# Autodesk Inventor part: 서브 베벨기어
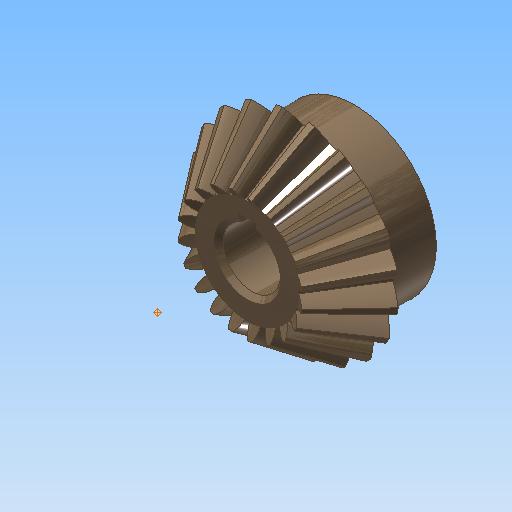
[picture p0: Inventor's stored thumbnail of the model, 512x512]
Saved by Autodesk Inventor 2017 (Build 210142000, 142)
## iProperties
Created: 2014-10
Part Number: 서브 베벨기어
Material: 강철, 탄소
Document SubType Name: Modeling
Designer: KYOUNG IL JANG
Categories: <?xml version="1.0" encoding="UTF-16"?> <MemberInstance><Categories><FamilyTemplate><FamilyTemplateParameter ValueType="xs:double" Id="1" ObjectReferenceKey="da
Mass: 135.037 g
Surface Area: 63.6518 cm^2
Volume: 17.1585 cm^3
Density: 7.87 g/cm^3
Appearance: 얼룩무늬
CustomPartVersion: 1
Revision Number: 1
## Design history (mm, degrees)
node "맨 위 점"
node "메쉬 평면2"
sketch "톱니 본체 스케치"
  geometry: L1 (0, 0)-(18.003, -31.331); L2 (18.003, -31.331)-(21.664, -28.891); L3 (21.664, -28.891)-(0, 0); L4 (20, -30)-(0, 0); L5 (10.813, -18.818)-(13.012, -17.352); L6 (18.003, -31.331)-(10.813, -18.818); L7 (21.664, -28.891)-(13.012, -17.352); L8 (0, -39.387)-(0, 6.564) reference; L9 (0, -30)-(21.664, -30)
  constraints: 16 end point, 4 point on line, 3 perpendicular, 2 collinear, 1 horizontal alignment, 1 vertical alignment
  dimensions: "d0" = 40 diameter of L4.start L8 (= da_de); "d1" = 36.00616 diameter of L1.end L8 (= da_dfe); "d2" = 43.3282 diameter of L2.end L8 (= da_dae); "d3" = 14.4 distance between parallel lines of L2 L5 (= da_b); "d4" = 28.8906 vertical distance of L2.end L1.start (= da_ve)
revolve "톱니 본체" sketch "톱니 본체 스케치" stored, may be unused: angle "d5" = 90 deg
node "시작점"
node "톱니 평면"
sketch "시작 스케치"
  geometry: L1 (0, -23.505)-(0, 10.645) reference; L2 (-0.834, -2.928)-(0.834, -2.928); A1 r 8.898 centre (-9.698, -3.713) between (-0.834, -2.928) and (-3.903, 3.04); A2 r 8.898 centre (9.698, -3.713) between (3.903, 3.04) and (0.834, -2.928); A3 r 27.357 centre (0, -24.037) between (3.903, 3.04) and (-3.903, 3.04); 1 further point
  constraints: 6 point on circle, 3 centre point, 3 symmetric about line, 2 end point, 1 coincident, 1 perpendicular, 1 other
  dimensions: "d7" = 8.89846 radius of A1 (= fd_rr); "d8" = 9.69794 horizontal distance of point (0, -24.037) A1.centre (= fd_x); "d9" = 20.32439 vertical distance of point (0, -24.037) A1.centre (= fd_y); "d57" = 27.35701 radius of A3 (= 0.5 x fd_dva + 0.3 x da_he); "d58" = 21.10901 distance from line of A3.centre L2 (= 0.5 x fd_dva - 1.12 x da_he)
node "끝점"
  node "끝 평면"
sketch "3D 스케치 오른쪽"
  node "Helical Curve Right" dims "d65" = 229.90621 (computed from da_dm, da_delta, da_beta), "d66" = 31.5, "d67" = 40 (= da_de), "d68" = -5.88003 (= -da_delta), "d69" = 12.16458 (computed from fd_loft, da_delta)
node "끝 평면 오른쪽"
sketch "끝 스케치 오른쪽"
  geometry: L1 (0, -22.649)-(0, 12.15) reference; L2 (-0.497, -1.72)-(0.497, -1.72); A1 r 5.299 centre (-5.775, -2.187) between (-0.497, -1.72) and (-2.324, 1.834); A2 r 5.299 centre (5.775, -2.187) between (2.324, 1.834) and (0.497, -1.72); A3 r 16.291 centre (0, -14.29) between (2.324, 1.834) and (-2.324, 1.834); 1 further point
  constraints: 6 point on circle, 3 centre point, 3 symmetric about line, 2 end point, 1 coincident, 1 perpendicular, 1 other
  dimensions: "d70" = 5.77526 horizontal distance of A3.centre A1.centre (computed from fd_x, fd_ratio); "d71" = 12.10346 vertical distance of point (0, -14.29) A1.centre (computed from fd_y, fd_ratio); "d72" = 5.29916 radius of A1 (computed from fd_rr, fd_ratio); "d73" = 12.57071 distance from line of point (0, -14.29) L2 (computed from d58, fd_ratio); "d74" = 16.29149 radius of A3 (computed from d57, fd_ratio)
feature "로프트 오른쪽" sketch "끝 스케치 오른쪽" dims "d75" = 0, "d77" = 0, "d79" = 0, "d80" = 90 deg, "d85" = 20, "d92" = 90 deg, "d93" = 90 deg, "da_teethtype" = 0 [user parameter]
sketch "3D 스케치 왼쪽"
  node "Helical Curve Left" dims "d26" = 229.90621 (computed from da_dm, da_delta, da_beta), "d27" = 12.16458 (computed from fd_loft, da_delta), "d28" = 40 (= da_de), "d29" = -5.88003 (= -da_delta)
node "끝 평면 왼쪽"
sketch "끝 스케치 왼쪽" dims "d56" = 10.82768 (derived)
  geometry: L1 (0, -35.087)-(0, 18.089) reference; L2 (-0.497, -1.716)-(0.497, -1.716); A1 r 5.299 centre (-5.775, -2.183) between (-0.497, -1.716) and (-2.324, 1.838); A2 r 5.299 centre (5.775, -2.183) between (2.324, 1.838) and (0.497, -1.716); A3 r 16.291 centre (0, -14.287) between (2.324, 1.838) and (-2.324, 1.838); 2 further points; 1 other entity
  constraints: 6 point on circle, 3 centre point, 3 symmetric about line, 2 end point, 1 coincident, 2 other
  dimensions: "d30" = 5.29916 radius of A1 (computed from fd_rr, fd_ratio); "d31" = 5.77526 horizontal distance of point (0, -14.287) A1.centre (computed from fd_x, fd_ratio); "d32" = 12.10346 vertical distance of A1.centre point (0, -14.287) (computed from fd_y, fd_ratio); "d61" = 16.29149 radius of A3 (computed from d57, fd_ratio); "d62" = 12.57071 distance from line of point (0, -14.287) L2 (computed from d58, fd_ratio)
feature "로프트 왼쪽" sketch "끝 스케치 왼쪽" dims "d35" = 0, "d37" = 0, "d39" = 0, "d40" = 90 deg, "d84" = 10, "d90" = 90 deg, "d91" = 90 deg, "da_teethtype" = 0 [user parameter]
sketch "본체 스케치"
  geometry: L1 (0, -35.038)-(0, -19.531) reference; L2 (18.003, -31.331)-(10.813, -18.818) reference; L3 (10.813, -18.818)-(0, -18.818); L4 (18.003, -31.331)-(0, -31.331)
  constraints: 4 end point, 2 perpendicular, 2 point on line
revolve "본체 고정" sketch "본체 스케치" stored, may be unused: angle "d46" = 90 deg
feature "피치 지름" dims angle "d47" = 90 deg
sketch "스케치8"
  geometry: C1 r 17 at (0, 0); 1 further point
  constraints: 1 centre point, 1 coincident
  dimensions: "d94" = 34 diameter of C1
extrude "돌출1" join sketch "스케치8" distance "d95" = 10; taper "d96" = 0 deg
sketch "스케치9"
  geometry: 1 further point
hole "구멍1" sketch "스케치9" at (0, 0) diameter "d97" = 12; stored, may be unused: countersink angle "d101" = 90 deg, drill point angle "d103" = 118 deg; dims "d98" = 6, "d99" = 4, "d100" = 2, "d102" = 8
sketch "스케치10"
  geometry: 1 further point
sketch "스케치11"
  geometry: 1 further point
sketch "스케치12"
  geometry: L1 (-2, 5.657)-(-2, 7.8); L2 (-2, 7.8)-(2, 7.8); L3 (2, 7.8)-(2, 5.657); A1 r 6 centre (0, 0) between (-2, 5.657) and (2, 5.657) reference; 1 further point
  constraints: 6 end point, 2 parallel, 2 point on circle, 1 perpendicular, 1 vertical
  dimensions: "d104" = 4 distance of L1.end L2.end; "d105" = 13.8 dimension on A1 L2
extrude "돌출2" cut sketch "스케치12" stored distance "d106" = 7; taper "d107" = 0 deg
chamfer "모따기1" distance "d108" = 1; stored, may be unused: second distance "d109" = 2, angle "d110" = 45 deg
body "Solid1"
feature "로프트" dims "d17" = 0, "d18" = 90 deg, "d19" = 0, "d20" = 90 deg, "d89" = 0, "da_teethtype" = 0 [user parameter]
pattern_circular "원형 패턴" dims angle "d22" = 360 deg, "d88" = 0, "da_teethtype" = 0 [user parameter]
pattern_circular "원형 패턴 오른쪽" dims angle "d82" = 360 deg, "da_teethtype" = 0 [user parameter]
pattern_circular "원형 패턴 왼쪽" dims angle "d42" = 360 deg, "da_teethtype" = 0 [user parameter]
sketch "끝 스케치"
  geometry: L1 (0, -15.359)-(0, 6.983) reference; L2 (-0.497, -1.72)-(0.497, -1.72); A1 r 5.299 centre (-5.775, -2.187) between (-0.497, -1.72) and (-2.324, 1.834); A2 r 5.299 centre (5.775, -2.187) between (2.324, 1.834) and (0.497, -1.72); A3 r 16.291 centre (0, -14.29) between (2.324, 1.834) and (-2.324, 1.834); 1 further point
  constraints: 6 point on circle, 3 centre point, 3 symmetric about line, 2 end point, 1 coincident, 1 other
  dimensions: "d12" = 5.29916 radius of A1 (computed from fd_rr, fd_ratio); "d15" = 5.77526 horizontal distance of A1.centre point (0, -14.29) (computed from fd_x, fd_ratio); "d16" = 12.10346 vertical distance of A1.centre point (0, -14.29) (computed from fd_y, fd_ratio); "d59" = 16.29149 radius of A3 (computed from d57, fd_ratio); "d60" = 12.57071 distance from line of A3.centre L2 (computed from d58, fd_ratio)
sketch "Sketch6"
  geometry: L1 (20, -30)-(0, 0) reference; L2 (0, -37.8)-(0, 6.3) reference
body "Srf1"
other parameters: "da_b" = 14.4 [user parameter; used in 2 equation terms], "da_de" = 40 [user parameter; used in 4 equation terms], "da_dae" = 43.3282 [user parameter; used in 2 equation terms], "da_dfe" = 36.00616 [user parameter; used in 1 equation term], "da_le" = 36.05551 [user parameter; used in 1 equation term], "da_omega" = 90 deg [user parameter; used in 1 equation term], "da_beta" = 0 [user parameter; used in 2 equation terms], "da_delta" = 5.88003 [user parameter; used in 8 equation terms], "da_alpha" = 20 deg [user parameter; used in 2 equation terms], "da_he" = 4.4 [user parameter; used in 4 equation terms], "da_ve" = 28.8906 [user parameter; used in 1 equation term], "fd_dv" = 48.07402 (computed from da_de, da_delta) [user parameter; used in 1 equation term], "fd_dva" = 52.07402 (computed from da_dae, da_delta) [user parameter; used in 3 equation terms], "fd_dvb" = 45.1748 (computed from fd_dv, da_alpha) [user parameter; used in 2 equation terms], "da_zv" = 240.37008 [user parameter; used in 1 equation term], "fd_loft" = 14.62 (= da_b + 0.05 x da_he) [user parameter; used in 4 equation terms], "fd_ratio" = 5.95514 (computed from da_le, fd_loft) [user parameter; used in 15 equation terms], "fd_rr" = 8.89846 (computed from fd_dd, fd_dvb) [user parameter; used in 6 equation terms], "fd_angle" = 0.66075 (computed from da_zv) [user parameter; used in 4 equation terms], "fd_x1" = 1.58709 (computed from da_dvw, fd_angle) [user parameter; used in 1 equation term], "fd_y1" = 23.98456 (computed from da_dvw, fd_angle) [user parameter; used in 1 equation term], "fd_x2" = 8.11084 (computed from fd_rr, fd_angle2, fd_angle) [user parameter; used in 1 equation term], "fd_y2" = 3.66016 (computed from fd_rr, fd_angle2, fd_angle) [user parameter; used in 1 equation term], "fd_x" = 9.69794 (= fd_x1 + fd_x2) [user parameter; used in 4 equation terms], "fd_y" = 20.32439 (= fd_y1 - fd_y2) [user parameter; used in 4 equation terms], "fd_angle2" = 3.57832 (computed from fd_dvb, fd_dd, da_alpha) [user parameter; used in 2 equation terms], "fd_dd" = 48.55402 (= fd_dva - 0.8 x da_he) [user parameter; used in 2 equation terms], "da_dvw" = 48.07402 [user parameter; used in 2 equation terms], "d11" = 14.62 (= fd_loft), "da_dm" = 32.01232 [user parameter; used in 2 equation terms], "da_x" = 0 [user parameter], "da_m" = 2 [user parameter], "d48" = 0, "d49" = 0, "d50" = 90 deg (= da_omega), "d51" = 9 deg (computed from da_z), "d52" = 0, "d53" = 0, "d54" = 0
